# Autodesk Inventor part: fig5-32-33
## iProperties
Shininess: 77.0
Angle Display Precision: 2
Document Length Units: 11269
Document Angle Units: 11279
Document Time Units: 11290
Document Mass Units: 11283
Document Length Units Precision: 3
Document Angle Units Precision: 2
Created: 2001-12
Part Number: fig5-32-33
Document SubType Name: Modeling
Designer: Renu Muthoo
Density: 1 g/cm^3
Density: 0.0
Volumn: 0.0
Area: 0.0
PropertySet Name: Model Information
Control State: 0
Master: False
Checked Out: False
Author: Renu Muthoo
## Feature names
1. Extrusion1
2. Extrusion3
3. Chamfer3
